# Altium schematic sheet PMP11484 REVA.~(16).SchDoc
size 431 x 279 mm; Date: Not shown in title block; ApprovedBy: Not shown in title block; CheckedBy: Not shown in title block; Author: Not shown in title block; CompanyName: Not shown in title block; Engineer: Not shown in title block; Organization: Not shown in title block; Address1: Not shown in title block; Address2: Not shown in title block; Address3: Not shown in title block; Address4: Not shown in title block; DocumentNumber: 1; Revision: Use project parameter SCH_Rev; SheetNumber: 1; SheetTotal: 1; PageSetup: Record=PageOptions¦CenterHorizontal=True¦CenterVertical=True¦PrintScale=1.00¦XCorrection=1.00¦YCorrection=1.00¦PrintKind=0¦BorderSize=5000000¦LeftOffset=0¦BottomOffset=0¦Orientation=2¦PaperLength=1000¦PaperWidth=1000¦Scale=100¦PaperSource=15¦PrintQuality=600¦MediaType=1¦DitherType=10¦PaperKind=Letter¦PrintScaleMode=1
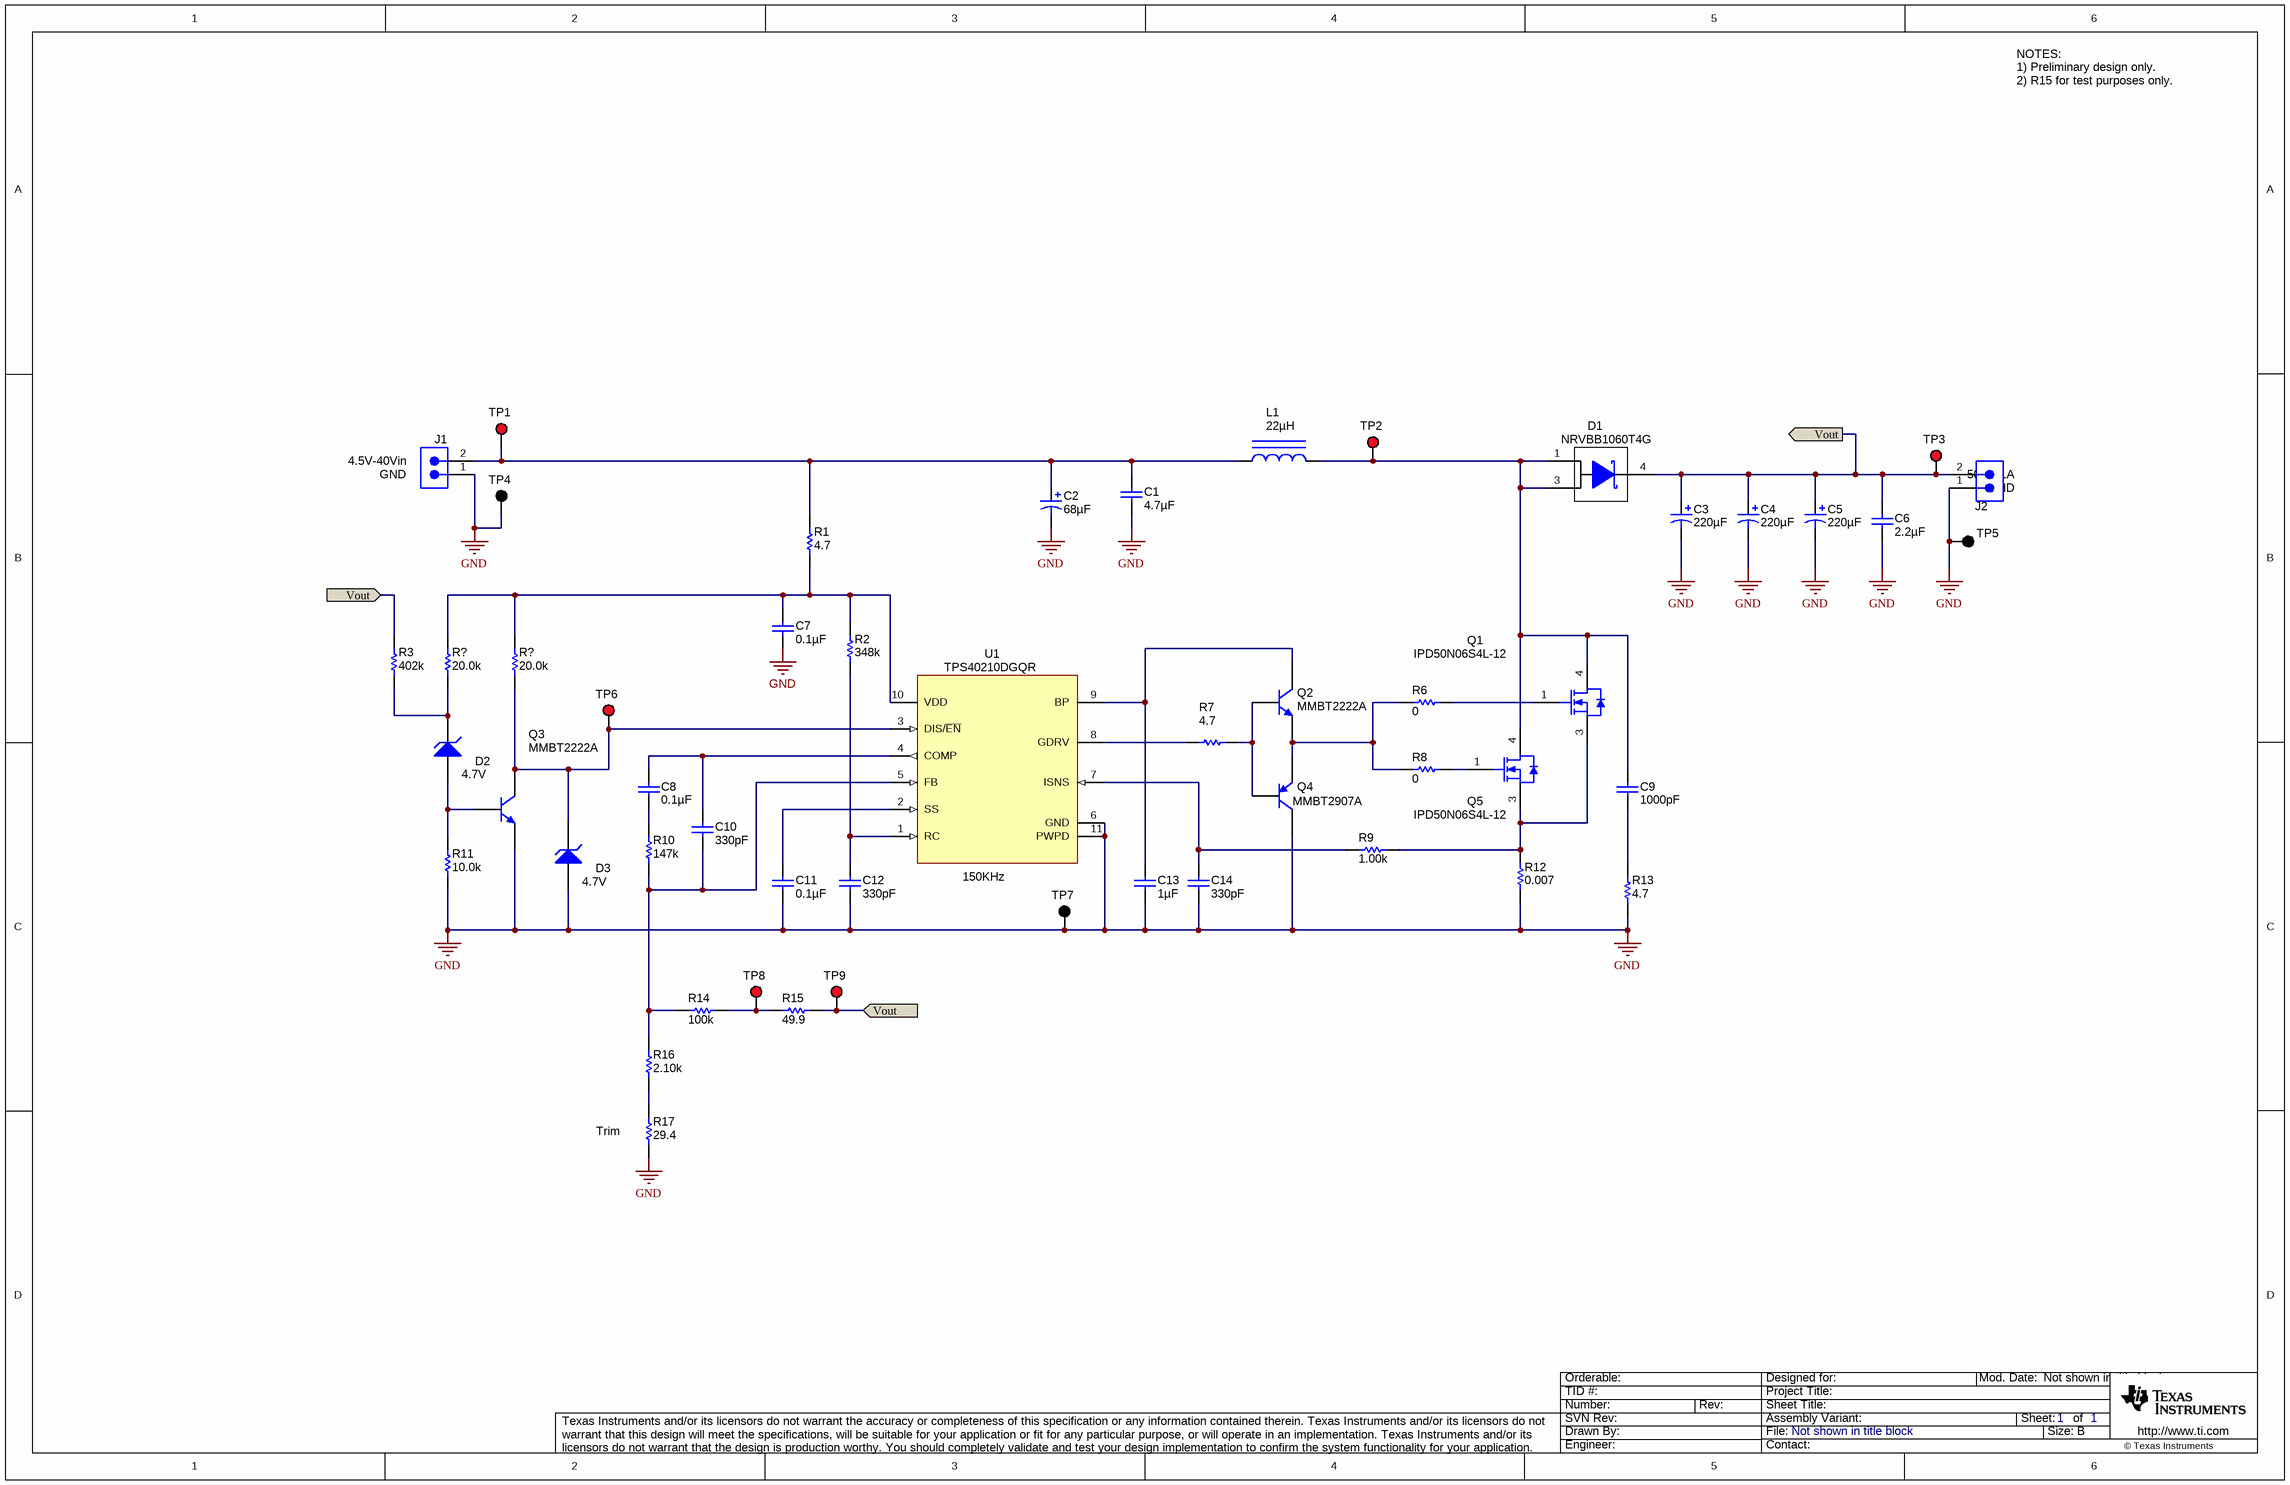
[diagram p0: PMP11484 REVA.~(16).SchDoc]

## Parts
(Parts that share a designator on the sheet are numbered #1, #2 ... from top to bottom, then left to right.)
C1  ValueDisplayed: 4.7µF  [1210]  (hidden comment: C3225X7R1H475M250AB)
C2  ValueDisplayed: 68µF  [SM_RADIAL_8MM]  (hidden comment: EEHZA1H680P)
C3  ValueDisplayed: 220µF  [BT_1250x2500]  (hidden comment: UBT1K221MHD1TO)
C4  ValueDisplayed: 220µF  [BT_1250x2500]  (hidden comment: UBT1K221MHD1TO)
C5  ValueDisplayed: 220µF  [BT_1250x2500]  (hidden comment: UBT1K221MHD1TO)
C6  ValueDisplayed: 2.2µF  [1210]  (hidden comment: GRM32ER72A225KA35L)
C7  ValueDisplayed: 0.1µF  [0603]  (hidden comment: C1608X7R1H104K)
C8  ValueDisplayed: 0.1µF  [0603]  (hidden comment: C1608X7R1H104K)
C9  ValueDisplayed: 1000pF  [0603]  (hidden comment: C1608C0G2A102J)
C10  ValueDisplayed: 330pF  [0603]  (hidden comment: C1608C0G1H331J)
C11  ValueDisplayed: 0.1µF  [0603]  (hidden comment: C1608X7R1H104K)
C12  ValueDisplayed: 330pF  [0603]  (hidden comment: C1608C0G1H331J)
C13  ValueDisplayed: 1µF  [0603]  (hidden comment: C1608X7R1C105K)
C14  ValueDisplayed: 330pF  [0603]  (hidden comment: C1608C0G1H331J)
D1  NRVBB1060T4G  [DDPAK]
D2  value 4.7V  [sod-323]  (hidden comment: MMSZ5230BS-7-F)
D3  value 4.7V  [sod-323]  (hidden comment: MMSZ5230BS-7-F)
J1  ED555/2DS  [TERM_BLK_ED555-2DS]  (value not drawn)
J2  ED555/2DS  [TERM_BLK_ED555-2DS]  (value not drawn)
L1  ValueDisplayed: 22µH  [IHLP8787MZ]  (hidden comment: IHLP8787MZER220M5A)
Q1  IPD50N06S4L-12  [DPAK]
Q2  MMBT2222A  [SOT-23]
Q3  MMBT2222A  [SOT-23]
Q4  MMBT2907A  [SOT-23]
Q5  IPD50N06S4L-12  [DPAK]
R1  value 4.7  [0603]  (hidden comment: CRCW06034R70JNEA)
R2  ValueDisplayed: 348k  [0603]  (hidden comment: CRCW0603348KFKEA)
R3  ValueDisplayed: 402k  [0603]  (hidden comment: CRCW0603402KFKEA)
R6  ValueDisplayed: 0  [0603]  (hidden comment: CRCW06030000Z0EA)
R7  value 4.7  [0603]  (hidden comment: CRCW06034R70JNEA)
R8  ValueDisplayed: 0  [0603]  (hidden comment: CRCW06030000Z0EA)
R9  value 1.00k  [0603]  (hidden comment: CRCW06031K00FKEA)
R10  ValueDisplayed: 147k  [0603]  (hidden comment: CRCW0603147KFKEA)
R11  ValueDisplayed: 10.0k  [0603]  (hidden comment: CRCW060310K0FKEA)
R12  ValueDisplayed: 0.007  [2512]  (hidden comment: WSL25127L000FEA)
R13  ValueDisplayed: 4.7  [1206]  (hidden comment: CRCW12064R70JNEA)
R14  value 100k  [0603]  (hidden comment: CRCW0603100KFKEA)
R15  value 49.9  [0603]  (hidden comment: CRCW060349R9FKEA)
R16  ValueDisplayed: 2.10k  [0603]  (hidden comment: CRCW06032K10FKEA)
R17  ValueDisplayed: 29.4  [0603]  (hidden comment: CRCW060329R4FKEA)
R?#1  ValueDisplayed: 20.0k  [0805_HV]  (hidden comment: CRCW080520K0FKEA)
R?#2  ValueDisplayed: 20.0k  [0805_HV]  (hidden comment: CRCW080520K0FKEA)
TP1  5000  [Keystone5000]  (value not drawn)
TP2  5000  [Keystone5000]  (value not drawn)
TP3  5000  [Keystone5000]  (value not drawn)
TP4  5001  [Keystone5001]  (value not drawn)
TP5  5001  [Keystone5001]  (value not drawn)
TP6  5000  [Keystone5000]  (value not drawn)
TP7  5001  [Keystone5001]  (value not drawn)
TP8  5000  [Keystone5000]  (value not drawn)
TP9  5000  [Keystone5000]  (value not drawn)
U1  TPS40210DGQR  [DGQ0010D_N]

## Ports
Vout

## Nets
GND: C1.1 C2.2(-) C3.2(-) C4.2(-) C5.2(-) C6.2 C7.2 C11.2 C12.2 C13.2 C14.2 D3.2(A) J1.1 J2.1 Q3.2(E) Q4.3(C) R11.1 R12.1 R13.1 R17.1 TP4.1 TP5.1 TP7.1 U1.6(GND) U1.11(PWPD)
Vout: C3.1(+) C4.1(+) C5.1(+) C6.1 D1.4(K) J2.2 R3.2 R15.1 TP3.1 TP9.1 ; port Vout
NetC1_2: C1.2 C2.1(+) J1.2 L1.1 R1.2 TP1.1
NetC7_1: C7.1 R1.1 R2.2 R?#1.2 R?#2.2 U1.10(VDD)
NetC8_1: C8.1 C10.2 U1.4(COMP)
NetC8_2: C8.2 R10.1
NetC9_1: C9.1 D1.1(A) D1.3(A) L1.2 Q1.4(D) Q5.4(D) TP2.1
NetC9_2: C9.2 R13.2
NetC10_1: C10.1 R10.2 R14.2 R16.2 U1.5(FB)
NetC11_1: C11.1 U1.2(SS)
NetC12_1: C12.1 R2.1 U1.1(RC)
NetC13_1: C13.1 Q2.3(C) U1.9(BP)
NetC14_1: C14.1 R9.2 U1.7(ISNS)
NetD2_1: D2.1(K) R3.1 R?#1.1
NetD2_2: D2.2(A) Q3.1(B) R11.2
NetD3_1: D3.1(K) Q3.3(C) R?#2.1 TP6.1 U1.3(DIS/~{EN})
NetQ1_1: Q1.1(G) R6.2
NetQ1_3: Q1.3(S) Q5.3(S) R9.1 R12.2
NetQ2_1: Q2.1(B) Q4.1(B) R7.2
NetQ2_2: Q2.2(E) Q4.2(E) R6.1 R8.1
NetQ5_1: Q5.1(G) R8.2
NetR7_1: R7.1 U1.8(GDRV)
NetR14_1: R14.1 R15.2 TP8.1
NetR16_1: R16.1 R17.2

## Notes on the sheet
- NOTES:
  1) Preliminary design only.
  2) R15 for test purposes only.
- (near J1) 4.5V-40Vin
- (near J1) GND
- (near J2) 50V@1A
- (near J2) GND
- (near U1) 150KHz
- (near R17) Trim

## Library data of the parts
C1 = C3225X7R1H335M: CAP, CERM, 4.7uF, 50V, +/-20%, X7R, 1210; Manufacturer: TDK; Polarized: N; CompType: Capacitor; U/M: EA; Cap_F: 0.0000033; Tolerance_%: 20; Value1: Unknown; VDC_V: 50; TaMin_C: -55; TaMax_C: 125
C2 = EEHZA1H680P: CAP, Polymer Hybrid, 68 µF, 50 V, +/- 20%, 30 ohm, 8x10 SMD; Manufacturer: Panasonic; Polarized: Y; CompType: Capacitor; Value: 68uF; U/M: EA; Cap_F: 0.000068; Tolerance_%: 20; Value1: 30 ohm; VDC_V: 50; Value2: 50V; ESR_ohm: 30; IRMS_A: 1.8; TaMin_C: -55; TaMax_C: 105; AEC Category: Q200
C3-C5 = UBT1H471MHD1TO: CAP, AL, 470 µF, 80 V, +/- 20%, 0.180 ohm, 1.24A, AEC-Q200 Grade 1, TH; Manufacturer: Nichicon; Polarized: Y; CompType: Capacitor; Value: 220uF; U/M: EA; Cap_F: 0.00047; Tolerance_%: 20; VDC_V: 80; Value2: 80V; TaMin_C: -40; TaMax_C: 125; Cap_Case: 12.5x25mm; AEC Category: Q200; AEC Grade: 1
C6 = GRM32ER72A225KA35L: CAP, CERM, 2.2 µF, 100 V, +/- 10%, X7R, 1210; Manufacturer: MuRata; Polarized: N; CompType: Capacitor; Value: 2.2uF; U/M: EA; Cap_F: 0.0000022; Tolerance_%: 10; ESR_ohm: 0.007; Value1: 0.007 ohm; VDC_V: 100; Value2: 100V; IRMS_A: 4.4; TaMin_C: -55; TaMax_C: 125; AEC Category: Q200
C7 C8 C11 = C1608X7R1H104K: CAP, CERM, 0.1uF, 50V, +/-10%, X7R, 0603; Manufacturer: TDK; Polarized: N; CompType: Capacitor; U/M: EA; Cap_F: 0.0000001; Tolerance_%: 10; ESR_Ohm: 0.017; Value1: 0.017 ohm; VDC_V: 50; TaMin_C: -55; TaMax_C: 125
C9 = C1608C0G2A102J: CAP, CERM, 1000 pF, 100 V, +/- 5%, C0G/NP0, 0603; Manufacturer: TDK; Polarized: N; CompType: Capacitor; Value: 1000pF; U/M: EA; Cap_F: 0.000000001; Tolerance_%: 5; ESR_ohm: 0.0589; Value1: 0.0589 ohm; VDC_V: 100; Value2: 100V; TaMin_C: -55; TaMax_C: 125; AEC Category: Q200
C10 C12 C14 = C1608C0G1H331J: CAP, CERM, 330 pF, 50 V, +/- 5%, C0G/NP0, 0603; Manufacturer: TDK; Polarized: N; CompType: Capacitor; Value: 330pF; U/M: EA; Cap_F: 0.00000000033; Tolerance_%: 5; ESR_ohm: 0.1096; Value1: 0.1096 ohm; VDC_V: 50; Value2: 50V; TaMin_C: -55; TaMax_C: 125; AEC Category: Q200
C13 = C1608X7R1C105K: CAP, CERM, 1uF, 16V, +/-10%, X7R, 0603; Manufacturer: TDK; Polarized: N; CompType: Capacitor; U/M: EA; Cap_F: 0.000001; Tolerance_%: 10; ESR_Ohm: 0.0057; Value1: 0.0057 ohm; VDC_V: 16; TaMin_C: -55; TaMax_C: 125
D1 = MBRB2515LT4G: Diode, Schottky, 60V, 10A, DDPAK; Manufacturer: ON Semi; U/M: EA; Vf_V: 0.6; Value2: 0.6V; Io_A: 10; Vr_V: 60; TJmax_C: 100; RJC_CperW: 1; AEC Category: Q101
D2 D3 = MMSZ5230BS-7-F: Diode, Zener, 4.7 V, 200 mW, SOD-323; Manufacturer: Diodes Inc.; U/M: EA; Power_W: 0.2; Vz_V: 4.7; Value1: 0.2W; RJA_CperW: 350; SymbolCreator: a0412235; AEC Category: Q101
J1 J2 = ED555/2DS: Terminal Block, 6A, 3.5mm Pitch, 2-Pos, TH; Manufacturer: On-Shore Technology, Inc.; SymbolCreator: a0412235; CompType: Connector; U/M: EA
L1 = IHLP8787MZE470M51: Inductor, Shielded, 22 µH, 16 A, 0.0106 ohm, SMD; Manufacturer: Vishay-Dale; Value: 22uH; Value2: 16A
Q1 Q5 = IPD50R280CE: MOSFET, N-CH, 60 V, 0.012 Ohms, AEC-Q101, DPAK; Manufacturer: Infineon Technologies; Alternate Manufacturer: None; U/M: EA; ChType: N; Value: 60V; VdsMax_V: 60; QgTyp_nC: 32.6; Vgs_V: 16; IdsMax_A: 13; AEC Category: Q101
Q2 Q3 = MMBT2222A, Fairchild Semiconductor: Transistor, NPN, 40 V, 0.15 A, SOT-23; CompType: BJT; PNP: 0; NPN: 1; Vceo_V: 40; Vcesat1_V: 0.3; Value: 40 V; IcRated_A: 0.15; Value1: 0.15 A; HfeMax: 300; TaMin_C: -55; TaMax_C: 150; U/M: EA; AEC Category: Q101
Q4 = MMBT2907A, Fairchild Semiconductor: Transistor, PNP, 60 V, 0.8 A, SOT-23; CompType: BJT; PNP: 1; NPN: 0; Vceo_V: 60; Vcesat1_V: 1.6; Value: 60 V; IcRated_A: 0.8; Value1: 0.8 A; HfeMax: 300; TaMin_C: -55; TaMax_C: 150; U/M: EA; AEC Category: Q101
R1 R7 = CRCW06034R70JNEA: RES, 4.7 ohm, 5%, 0.1W, 0603; Manufacturer: Vishay-Dale; CompType: Resistor; Value_Code: 4R70; Tolerance_%: 5; Power_W: 0.1; VDC_V: 75; TempCo: 200 ppm/C; EIA_Code: E24; U/M: EA
R2 = CRCW0603348KFKEA: RES, 348 k, 1%, 0.1 W, 0603; Manufacturer: Vishay-Dale; CompType: Resistor; Value: 348k; Res_ohm: 348000; Tolerance_%: 1; Power_W: 0.1; Value2: 0.1W; VDC_V: 75; TempCo: 100 ppm/C; EIA_Code: E96; U/M: EA; AEC Category: Q200
R3 = CRCW0603402KFKEA: RES, 402 k, 1%, 0.1 W, 0603; Manufacturer: Vishay-Dale; CompType: Resistor; Value: 402k; Res_ohm: 402000; Tolerance_%: 1; Power_W: 0.1; Value2: 0.1W; VDC_V: 75; TempCo: 100 ppm/C; EIA_Code: E96; U/M: EA; AEC Category: Q200
R6 R8 = CRCW06030000Z0EA: RES, 0, 5%, 0.1 W, 0603; Manufacturer: Vishay-Dale; CompType: Resistor; Value: 0; Value_Code: 0000; Tolerance_%: 5; Power_W: 0.1; Value2: 0.1W; VDC_V: 75; TempCo: 200 ppm/C; EIA_Code: E24; U/M: EA; AEC Category: Q200
R9 = CRCW06031K00FKEA: RES, 1.00k ohm, 1%, 0.1W, 0603; Manufacturer: Vishay-Dale; CompType: Resistor; Res_ohm: 1000; Value_Code: 1k00; Tolerance_%: 1; Power_W: 0.1; VDC_V: 75; TempCo: 100 ppm/C; EIA_Code: E96; U/M: EA
R10 = CRCW0603147KFKEA: RES, 147 k, 1%, 0.1 W, 0603; Manufacturer: Vishay-Dale; CompType: Resistor; Value: 147k; Res_ohm: 147000; Tolerance_%: 1; Power_W: 0.1; Value2: 0.1W; VDC_V: 75; TempCo: 100 ppm/C; EIA_Code: E96; U/M: EA; AEC Category: Q200
R11 = CRCW060310K0FKEA: RES, 10.0 k, 1%, 0.1 W, 0603; Manufacturer: Vishay-Dale; CompType: Resistor; Value: 10.0k; Res_ohm: 10000; Value_Code: 10k0; Tolerance_%: 1; Power_W: 0.1; Value2: 0.1W; VDC_V: 75; TempCo: 100 ppm/C; EIA_Code: E96; U/M: EA; AEC Category: Q200
R12 = WSL25129L000FEA18: RES, 0.007, 1%, 2 W, 2512; Manufacturer: Vishay-Dale; CompType: Resistor; Value: 0.007; Value_Code: 7L000; Tolerance_%: 1; Power_W: 2; Value2: 2W; TempCo: 75 ppm/C; EIA_Code: E96; U/M: EA; AEC Category: Q200
R13 = CRCW12064R70JNEA: RES, 4.7, 5%, 0.25 W, 1206; Manufacturer: Vishay-Dale; CompType: Resistor; Value: 4.7; Value_Code: 4R70; Tolerance_%: 5; Power_W: 0.25; Value2: 0.25W; VDC_V: 200; TempCo: 200 ppm/C; EIA_Code: E24; U/M: EA; AEC Category: Q200
R14 = CRCW0603100KFKEA: RES, 100k ohm, 1%, 0.1W, 0603; Manufacturer: Vishay-Dale; CompType: Resistor; Res_ohm: 100000; Tolerance_%: 1; Power_W: 0.1; VDC_V: 75; TempCo: 100 ppm/C; EIA_Code: E96; U/M: EA
R15 = CRCW060349R9FKEA: RES, 49.9 ohm, 1%, 0.1W, 0603; Manufacturer: Vishay-Dale; CompType: Resistor; Value_Code: 49R9; Tolerance_%: 1; Power_W: 0.1; VDC_V: 75; TempCo: 100 ppm/C; EIA_Code: E96; U/M: EA
R16 = CRCW06032K10FKEA: RES, 2.10 k, 1%, 0.1 W, 0603; Manufacturer: Vishay-Dale; CompType: Resistor; Value: 2.10k; Res_ohm: 2100; Value_Code: 2k10; Tolerance_%: 1; Power_W: 0.1; Value2: 0.1W; VDC_V: 75; TempCo: 100 ppm/C; EIA_Code: E96; U/M: EA; AEC Category: Q200
R17 = CRCW060329R4FKEA: RES, 29.4, 1%, 0.1 W, 0603; Manufacturer: Vishay-Dale; CompType: Resistor; Value: 29.4; Value_Code: 29R4; Tolerance_%: 1; Power_W: 0.1; Value2: 0.1W; VDC_V: 75; TempCo: 100 ppm/C; EIA_Code: E96; U/M: EA; AEC Category: Q200
R?#1 R?#2 = CRCW080520K0FKEA: RES, 20.0 k, 1%, 0.125 W, 0805; Manufacturer: Vishay-Dale; CompType: Resistor; Value: 20.0k; Res_ohm: 20000; Value_Code: 20k0; Tolerance_%: 1; Power_W: 0.125; Value2: 0.125W; VDC_V: 150; TempCo: 100 ppm/C; EIA_Code: E96; U/M: EA; AEC Category: Q200
TP1-TP3 TP6 TP8 TP9 = 5000: Test Point, TH, Miniature, Red; Manufacturer: Keystone; CompType: Test Point Loop; U/M: EA
TP4 TP5 TP7 = 5001: Test Point, TH, Miniature, Black; Manufacturer: Keystone; CompType: Test Point Loop; U/M: EA
U1 = TPS40210DGQR: 4.5-V TO 52-V INPUT CURRENT MODE BOOST CONTROLLER, DGQ0010D; Manufacturer: Texas Instruments; SymbolCreator: a0412235; CompType: IC; U/M: EA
